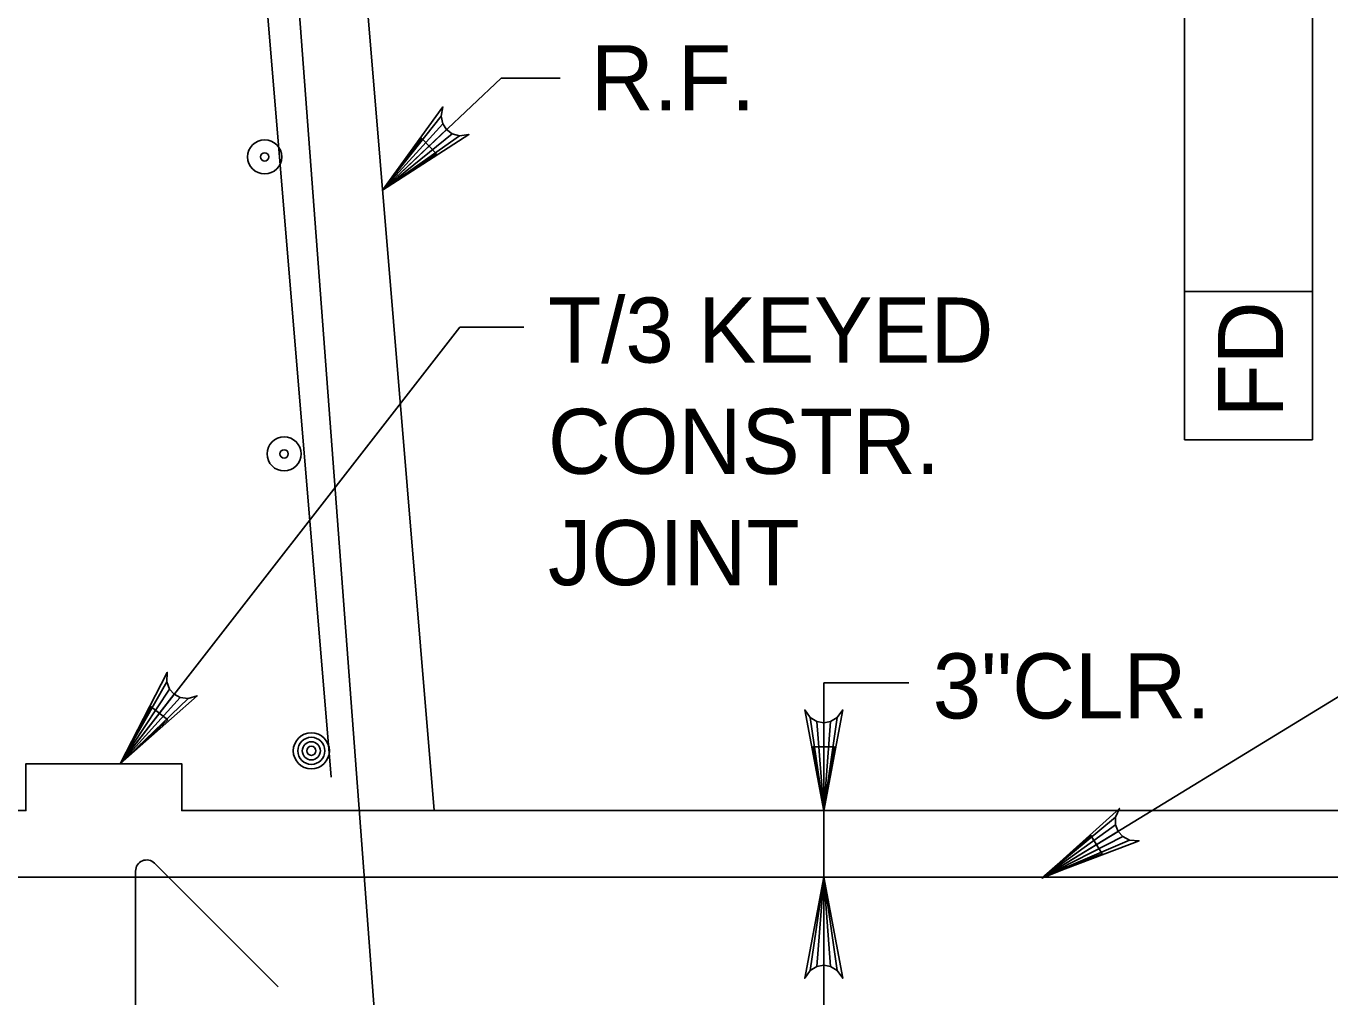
# Model space of a CAD drawing. Extents: x 638340 to 640242, y 295465 to 298435.
# Drawn here: x 639139.2 to 639199.2, y 295843.7 to 295888.4 of the extents above; entities that cross this region are included whole.
import ezdxf

# ---------------------------------------------------------------- set-up
doc = ezdxf.new("R2010")
doc.units = 0
for name, color, linetype in [('3', 7, 'Continuous'), ('Level 3', 7, 'Continuous'), ('Level 4', 7, 'Continuous'), ('Level 6', 7, 'Continuous'), ('Level 7', 7, 'Continuous'), ('Level 9', 7, 'Continuous')]:
    doc.layers.add(name, color=color, linetype=linetype)

# ---------------------------------------------------------------- blocks, each defined once
blk = doc.blocks.new('B')
at = {"layer": '3'}
blk.add_circle((0, 0), 0.16, dxfattribs=at)
for start, end in [(0, 180), (180, 0)]:
    blk.add_arc((0, 0), 0.0391, start, end, dxfattribs=at)

msp = doc.modelspace()

# ---------------------------------------------------------------- linework, layer by layer
at = {"layer": 'Level 4'}
for p, q in [((639192.524, 295869.351), (639192.524, 295904.583)), ((639198.419, 295904.583), (639198.419, 295869.351)), ((639155.592, 295880.852), (639161.048, 295886.006)), ((639161.048, 295886.006), (639163.777, 295886.006)), ((639198.419, 295876.181), (639192.524, 295876.181)), ((639143.511, 295854.421), (639159.152, 295874.534)), ((639159.152, 295874.534), (639162.098, 295874.534)), ((639198.419, 295869.351), (639192.524, 295869.351)), ((639186.009, 295849.19), (639205.179, 295860.931)), ((639186.009, 295849.19), (639205.179, 295860.931)), ((639175.91, 295849.191), (639175.91, 295858.149)), ((639175.91, 295858.149), (639179.823, 295858.149)), ((639175.91, 295858.148), (639175.91, 295840.981))]:
    msp.add_line(p, q, dxfattribs=at)
for points in [[(639155.592, 295880.852), (639158.374, 295884.68), (639158.285, 295884.253), (639158.364, 295883.9), (639158.539, 295883.636), (639158.792, 295883.447), (639159.142, 295883.347), (639159.572, 295883.411), (639155.592, 295880.852), (639159.142, 295883.347), (639158.792, 295883.447), (639155.592, 295880.852), (639158.539, 295883.636), (639158.364, 295883.9), (639155.592, 295880.852), (639158.285, 295884.253)], [(639143.511, 295854.421), (639145.678, 295858.627), (639145.655, 295858.193), (639145.786, 295857.856), (639146, 295857.621), (639146.279, 295857.473), (639146.638, 295857.428), (639147.054, 295857.556), (639143.511, 295854.421), (639146.638, 295857.428), (639146.279, 295857.473), (639143.511, 295854.421), (639146, 295857.621), (639145.786, 295857.856), (639143.511, 295854.421), (639145.655, 295858.193)], [(639175.91, 295852.254), (639175.038, 295856.906), (639175.286, 295856.548), (639175.598, 295856.363), (639175.91, 295856.309), (639176.222, 295856.363), (639176.533, 295856.548), (639176.781, 295856.906), (639175.91, 295852.254), (639176.533, 295856.548), (639176.222, 295856.363), (639175.91, 295852.254), (639175.91, 295856.309), (639175.598, 295856.363), (639175.91, 295852.254), (639175.286, 295856.548)], [(639186.009, 295849.191), (639189.521, 295852.364), (639189.344, 295851.965), (639189.349, 295851.603), (639189.467, 295851.308), (639189.675, 295851.071), (639189.995, 295850.902), (639190.432, 295850.878), (639186.009, 295849.191), (639189.995, 295850.902), (639189.675, 295851.071), (639186.009, 295849.191), (639189.467, 295851.308), (639189.349, 295851.603), (639186.009, 295849.191), (639189.344, 295851.965)], [(639186.009, 295849.191), (639189.521, 295852.364), (639189.344, 295851.965), (639189.349, 295851.603), (639189.467, 295851.308), (639189.675, 295851.071), (639189.995, 295850.902), (639190.432, 295850.878), (639186.009, 295849.191), (639189.995, 295850.902), (639189.675, 295851.071), (639186.009, 295849.191), (639189.467, 295851.308), (639189.349, 295851.603), (639186.009, 295849.191), (639189.344, 295851.965)], [(639175.91, 295849.191), (639176.781, 295844.54), (639176.533, 295844.897), (639176.222, 295845.082), (639175.91, 295845.136), (639175.598, 295845.082), (639175.286, 295844.897), (639175.038, 295844.54), (639175.91, 295849.191), (639175.286, 295844.897), (639175.598, 295845.082), (639175.91, 295849.191), (639175.91, 295845.136), (639176.222, 295845.082), (639175.91, 295849.191), (639176.533, 295844.897)]]:
    msp.add_lwpolyline(points, dxfattribs=at)
for points in [[(639158.073, 295882.519), (639157.397, 295883.232), (639155.592, 295880.852)], [(639145.707, 295856.446), (639144.931, 295857.049), (639143.511, 295854.421)], [(639176.4, 295855.201), (639175.417, 295855.201), (639175.91, 295852.254)], [(639188.725, 295850.277), (639188.211, 295851.115), (639185.955, 295849.156)], [(639188.725, 295850.277), (639188.211, 295851.115), (639185.955, 295849.156)]]:
    msp.add_lwpolyline(points, close=True, dxfattribs=at)
at = {"layer": 'Level 6'}
for p, q in [((639149.683, 295896.322), (639153.226, 295853.797)), ((639151.201, 295896.576), (639156.341, 295828.1)), ((639144.218, 295849.48), (639144.218, 295825.133)), ((639150.785, 295844.149), (639145.091, 295849.842)), ((639208.3, 295849.191), (639100.676, 295849.191))]:
    msp.add_line(p, q, dxfattribs=at)
for radius in [0.832, 0.624, 0.416, 0.208]:
    msp.add_circle((639152.313, 295855.018), radius, dxfattribs=at)
msp.add_arc((639144.729, 295849.479), 0.511, 45, 180, dxfattribs=at)
at = {"layer": 'Level 7'}
msp.add_lwpolyline([(639128.159, 295852.262), (639139.169, 295852.262), (639139.169, 295854.421), (639146.347, 295854.421), (639146.347, 295852.262), (639157.975, 295852.262)], dxfattribs=at)
at = {"layer": 'Level 9'}
for p in [(639146.643, 295988.253), (639211.515, 295852.262), (639211.515, 295852.262), (639211.515, 295852.262)]:
    msp.add_line(p, (639157.975, 295852.262), dxfattribs=at)

# ---------------------------------------------------------------- block references
at = {"layer": 'Level 3', "xscale": 4.911876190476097, "yscale": 4.911876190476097, "rotation": 90}
for p in [(639150.163, 295882.378), (639151.059, 295868.698)]:
    msp.add_blockref('B', p, dxfattribs=at)

# ---------------------------------------------------------------- texts
at = {"layer": 'Level 3'}
msp.add_text('3"CLR.', height=3.0001, dxfattribs=at).set_placement((639180.927, 295856.508))
at = {"layer": 'Level 4'}
for s, p in [('R.F.', (639165.182, 295884.524)), ('T/3 KEYED', (639163.209, 295872.902)), ('CONSTR.', (639163.209, 295867.777)), ('JOINT', (639163.209, 295862.649))]:
    msp.add_text(s, height=3.0001, dxfattribs=at).set_placement(p)
msp.add_text('FD', height=3.0001, rotation=90, dxfattribs=at).set_placement((639197.065, 295870.373))

doc.saveas('drawing.dxf')
